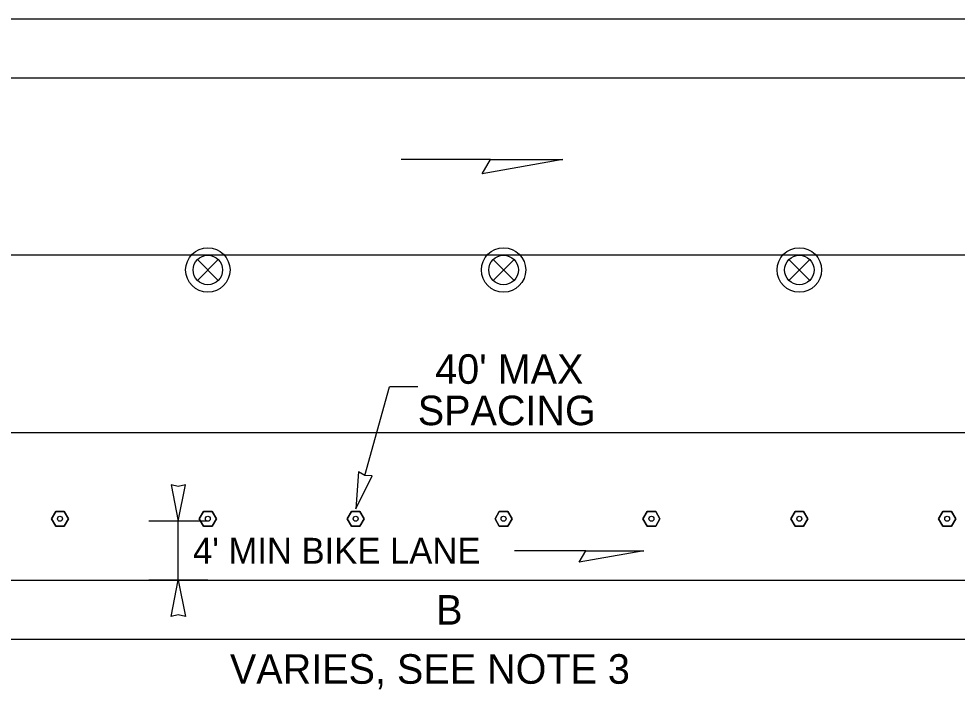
# Model space of a CAD drawing. Extents: x 99958 to 100136, y 99935 to 100013.
# Drawn here: x 100007.579 to 100010.117, y 99974.941 to 99976.756 of the extents above; entities that cross this region are included whole.
import ezdxf

# ---------------------------------------------------------------- set-up
doc = ezdxf.new("R2010")
doc.units = 0
for name, color, linetype in [('RD_ED_ShoulderPavedEdge', 7, 'Continuous'), ('RD_MK_LineEdgeWhite', 7, 'Continuous'), ('RD_MK_LineEdgeYellow', 7, 'Continuous'), ('RD_MK_LineLane', 7, 'Continuous'), ('TR_WZ_TrafficSafetyDrum', 7, 'Continuous'), ('TR_WZ_TubularMarker', 7, 'Continuous'), ('TR_WZ_WorkZoneDetails', 7, 'Continuous'), ('TR_WZ_WorkZoneTextCurrent', 7, 'Continuous')]:
    doc.layers.add(name, color=color, linetype=linetype)

msp = doc.modelspace()

# ---------------------------------------------------------------- linework, layer by layer
at = {"layer": 'RD_ED_ShoulderPavedEdge'}
for p, q in [((100000.8283, 99976.7557), (100015.62, 99976.7557)), ((100000.8283, 99975.2357), (100015.62, 99975.2357))]:
    msp.add_line(p, q, dxfattribs=at)
at = {"layer": 'RD_MK_LineEdgeWhite'}
msp.add_line((100000.8283, 99975.6357), (100015.62, 99975.6357), dxfattribs=at)
at = {"layer": 'RD_MK_LineEdgeYellow'}
msp.add_line((100000.8283, 99976.5957), (100015.62, 99976.5957), dxfattribs=at)
at = {"layer": 'RD_MK_LineLane'}
msp.add_lwpolyline([(100015.62, 99976.1157), (100000.8283, 99976.1157)], dxfattribs=at)
at = {"layer": 'TR_WZ_TrafficSafetyDrum'}
for p, q in [((100008.062, 99976.104), (100008.1186, 99976.0474)), ((100008.1186, 99976.104), (100008.062, 99976.0474)), ((100008.862, 99976.104), (100008.9186, 99976.0474)), ((100008.9186, 99976.104), (100008.862, 99976.0474)), ((100009.662, 99976.104), (100009.7186, 99976.0474)), ((100009.7186, 99976.104), (100009.662, 99976.0474))]:
    msp.add_line(p, q, dxfattribs=at)
for centre, radius in [((100008.0903, 99976.0757), 0.06), ((100008.0903, 99976.0757), 0.06), ((100008.0903, 99976.0757), 0.04), ((100008.8903, 99976.0757), 0.06), ((100008.8903, 99976.0757), 0.06), ((100008.8903, 99976.0757), 0.04), ((100009.6903, 99976.0757), 0.06), ((100009.6903, 99976.0757), 0.06), ((100009.6903, 99976.0757), 0.04)]:
    msp.add_circle(centre, radius, dxfattribs=at)
at = {"layer": 'TR_WZ_TubularMarker'}
for points in [[(100007.6672, 99975.4024), (100007.6787, 99975.4224), (100007.7018, 99975.4224), (100007.7134, 99975.4024), (100007.7018, 99975.3824), (100007.6787, 99975.3824)], [(100008.0672, 99975.4024), (100008.0787, 99975.4224), (100008.1018, 99975.4224), (100008.1134, 99975.4024), (100008.1018, 99975.3824), (100008.0787, 99975.3824)], [(100008.4672, 99975.4024), (100008.4787, 99975.4224), (100008.5018, 99975.4224), (100008.5134, 99975.4024), (100008.5018, 99975.3824), (100008.4787, 99975.3824)], [(100008.8672, 99975.4024), (100008.8787, 99975.4224), (100008.9018, 99975.4224), (100008.9134, 99975.4024), (100008.9018, 99975.3824), (100008.8787, 99975.3824)], [(100009.2672, 99975.4024), (100009.2787, 99975.4224), (100009.3018, 99975.4224), (100009.3134, 99975.4024), (100009.3018, 99975.3824), (100009.2787, 99975.3824)], [(100009.6672, 99975.4024), (100009.6787, 99975.4224), (100009.7018, 99975.4224), (100009.7134, 99975.4024), (100009.7018, 99975.3824), (100009.6787, 99975.3824)], [(100010.0672, 99975.4024), (100010.0787, 99975.4224), (100010.1018, 99975.4224), (100010.1134, 99975.4024), (100010.1018, 99975.3824), (100010.0787, 99975.3824)]]:
    msp.add_lwpolyline(points, close=True, dxfattribs=at)
for points in [[(100007.6787, 99975.3824), (100007.7018, 99975.3824), (100007.7134, 99975.4024), (100007.7018, 99975.4224), (100007.6787, 99975.4224), (100007.6672, 99975.4024), (100007.6787, 99975.3824)], [(100008.0787, 99975.3824), (100008.1018, 99975.3824), (100008.1134, 99975.4024), (100008.1018, 99975.4224), (100008.0787, 99975.4224), (100008.0672, 99975.4024), (100008.0787, 99975.3824)], [(100008.4787, 99975.3824), (100008.5018, 99975.3824), (100008.5134, 99975.4024), (100008.5018, 99975.4224), (100008.4787, 99975.4224), (100008.4672, 99975.4024), (100008.4787, 99975.3824)], [(100008.8787, 99975.3824), (100008.9018, 99975.3824), (100008.9134, 99975.4024), (100008.9018, 99975.4224), (100008.8787, 99975.4224), (100008.8672, 99975.4024), (100008.8787, 99975.3824)], [(100009.2787, 99975.3824), (100009.3018, 99975.3824), (100009.3134, 99975.4024), (100009.3018, 99975.4224), (100009.2787, 99975.4224), (100009.2672, 99975.4024), (100009.2787, 99975.3824)], [(100009.6787, 99975.3824), (100009.7018, 99975.3824), (100009.7134, 99975.4024), (100009.7018, 99975.4224), (100009.6787, 99975.4224), (100009.6672, 99975.4024), (100009.6787, 99975.3824)], [(100010.0787, 99975.3824), (100010.1018, 99975.3824), (100010.1134, 99975.4024), (100010.1018, 99975.4224), (100010.0787, 99975.4224), (100010.0672, 99975.4024), (100010.0787, 99975.3824)]]:
    msp.add_lwpolyline(points, dxfattribs=at)
for centre in [(100007.6903, 99975.4024), (100008.0903, 99975.4024), (100008.4903, 99975.4024), (100008.8903, 99975.4024), (100009.2903, 99975.4024), (100009.6903, 99975.4024), (100010.0903, 99975.4024)]:
    msp.add_circle(centre, 0.00667, dxfattribs=at)
at = {"layer": 'TR_WZ_WorkZoneDetails'}
for p, q in [((100008.8545, 99976.375), (100008.6134, 99976.375)), ((100008.5153, 99975.5194), (100008.5819, 99975.7596)), ((100008.6582, 99975.7596), (100008.582, 99975.7596)), ((100008.0903, 99975.3957), (100007.9303, 99975.3957)), ((100008.0103, 99975.2357), (100008.0103, 99975.3957)), ((100009.1128, 99975.3157), (100008.9199, 99975.3157)), ((100008.0903, 99975.2357), (100007.9303, 99975.2357)), ((100010.1965, 99975.0757), (100007.384, 99975.0757))]:
    msp.add_line(p, q, dxfattribs=at)
for points in [[(100009.051, 99976.375), (100008.8322, 99976.3364), (100008.8545, 99976.375)], [(100008.4903, 99975.4291), (100008.5351, 99975.5187), (100008.5153, 99975.5194), (100008.4979, 99975.5289)], [(100008.0103, 99975.3957), (100008.0296, 99975.494), (100008.0103, 99975.4895), (100007.991, 99975.494)], [(100009.2701, 99975.3157), (100009.095, 99975.2849), (100009.1128, 99975.3157)], [(100008.0103, 99975.2357), (100008.0296, 99975.1374), (100008.0103, 99975.142), (100007.991, 99975.1374)]]:
    msp.add_lwpolyline(points, close=True, dxfattribs=at)

# ---------------------------------------------------------------- texts
at = {"layer": 'TR_WZ_WorkZoneTextCurrent'}
for s, height, p in [("40' MAX", 0.08, (100008.7053, 99975.7676)), ('SPACING', 0.08, (100008.6582, 99975.6556)), ("4' MIN BIKE LANE", 0.07, (100008.0503, 99975.2807))]:
    msp.add_text(s, height=height, dxfattribs=at).set_placement(p)
for s, p in [('B', (100008.7079, 99975.1157)), ('VARIES, SEE NOTE 3', (100008.15, 99974.9557))]:
    msp.add_text(s, height=0.08, rotation=360, dxfattribs=at).set_placement(p)

doc.saveas('drawing.dxf')
